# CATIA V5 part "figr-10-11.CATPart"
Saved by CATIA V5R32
Part number: Part1
Bounding box of the stored display mesh (mm): x -100 to 0, y -100 to 90, z 0 to 33.608
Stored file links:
  D:\PROJECTS\Project 2022\CATIA V5 6R 2022\Resources\Part Files\c10_catia_v5_6r2022_prt\c10_catia_v5_6r2022_prt\figr-10-11.CATPart
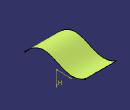
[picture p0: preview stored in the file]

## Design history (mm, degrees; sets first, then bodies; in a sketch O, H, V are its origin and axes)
Set1
  Sketch1 on face of yz-plane, origin (0, 0, 0), H (0, 0, -1), V (0, 1, 0)
    spline S1 through (0, -100) (-30, -20) (-10, 30) (-20, 90)
  Extrude1: Element1 Sketch1, Lim1 0, Lim2 100, Direction face of yz-plane
Body1 (main body)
